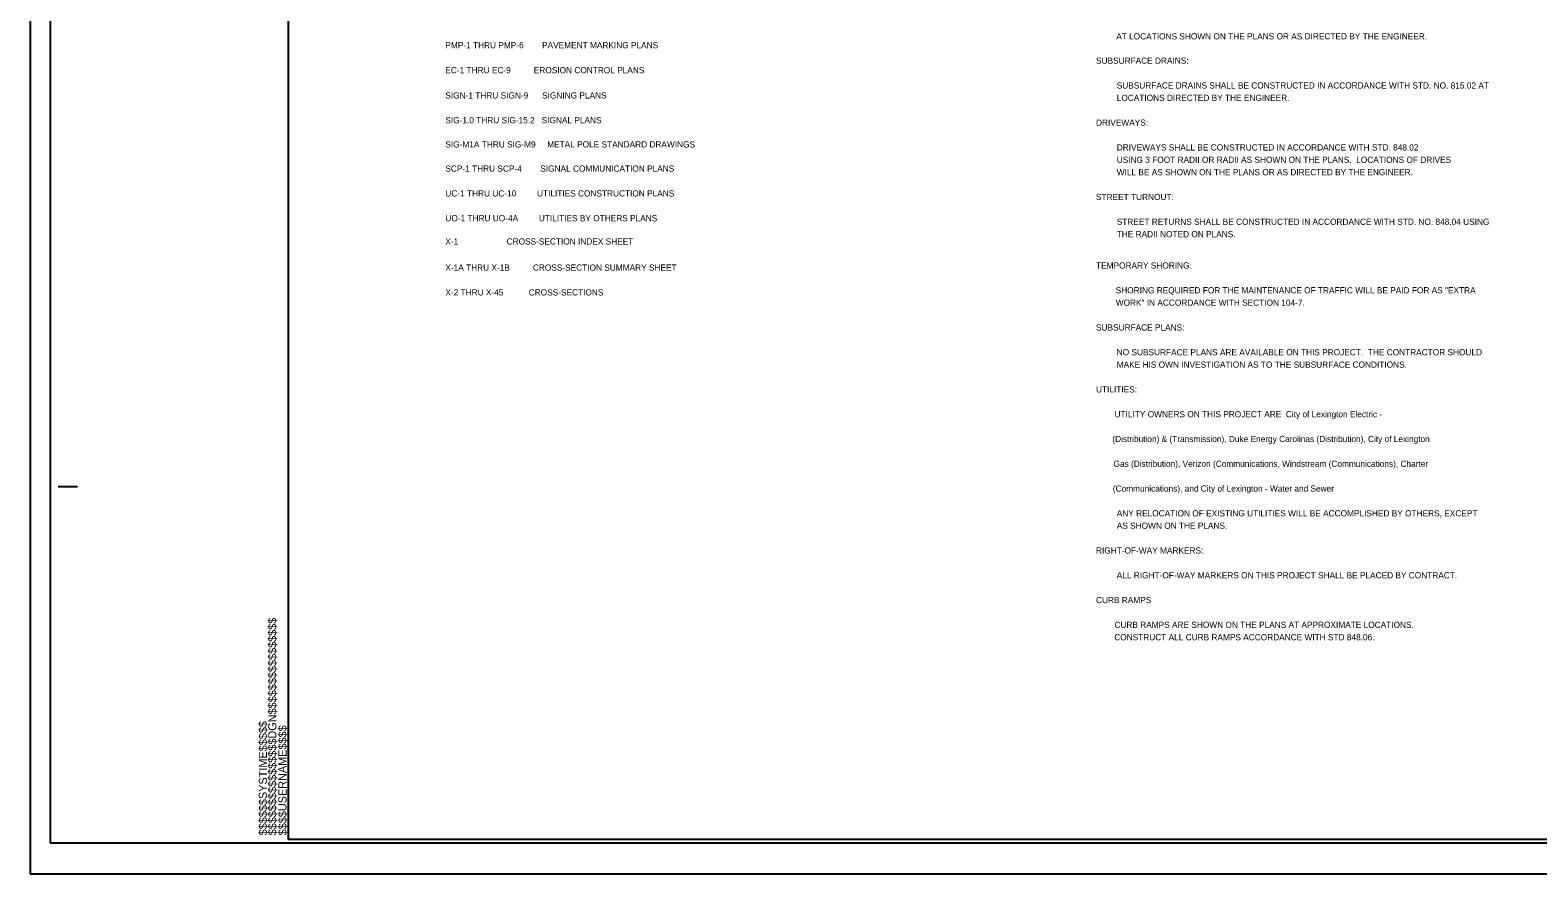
# Model space of a CAD drawing. Extents: x 1537922 to 1539606, y 409903 to 410998.
# Drawn here: x 1537922 to 1538895, y 409903 to 410448 of the extents above; entities that cross this region are included whole.
import ezdxf

# ---------------------------------------------------------------- set-up
doc = ezdxf.new("R2010")
doc.units = 0
for name, color, linetype in [('Default', 7, 'Continuous'), ('Sheet Cutting Line CELL', 7, 'Continuous'), ('Sheet Plan CELL', 7, 'Continuous'), ('Sheet Plot Border Inside CELL', 7, 'Continuous'), ('Sheet Plot Border Outside CELL', 7, 'Continuous')]:
    doc.layers.add(name, color=color, linetype=linetype)

msp = doc.modelspace()

# ---------------------------------------------------------------- linework, layer by layer
at = {"layer": 'Sheet Cutting Line CELL'}
for p, q in [((1537922.37, 410998.35), (1537922.37, 409903.35)), ((1537922.37, 409903.35), (1539605.87, 409903.35))]:
    msp.add_line(p, q, dxfattribs=at)
at = {"layer": 'Sheet Plan CELL'}
for p, q in [((1537940.37, 410153.35), (1537952.87, 410153.35)), ((1538088.87, 409925.85), (1538088.87, 409925.85))]:
    msp.add_line(p, q, dxfattribs=at)
msp.add_lwpolyline([(1539588.87, 410975.85), (1538088.87, 410975.85), (1538088.87, 409925.85), (1539588.87, 409925.85)], close=True, dxfattribs=at)
at = {"layer": 'Sheet Plot Border Inside CELL'}
msp.add_lwpolyline([(1537935.37, 409923.35), (1539601.37, 409923.35), (1539601.37, 410978.35), (1537935.37, 410978.35)], close=True, dxfattribs=at)
at = {"layer": 'Sheet Plot Border Outside CELL'}
msp.add_lwpolyline([(1537922.37, 409903.35), (1539605.87, 409903.35), (1539605.87, 410998.35), (1537922.37, 410998.35)], close=True, dxfattribs=at)

# ---------------------------------------------------------------- texts
at = {"layer": 'Default'}
for s, p in [('         AT LOCATIONS SHOWN ON THE PLANS OR AS DIRECTED BY THE ENGINEER.', (1538609.77, 410442.07)), ('PMP-1 THRU PMP-6        PAVEMENT MARKING PLANS', (1538190.28, 410436.34)), ('EC-1 THRU EC-9          EROSION CONTROL PLANS', (1538190.28, 410420.24)), ('SUBSURFACE DRAINS:', (1538610.1, 410426.36)), ('         SUBSURFACE DRAINS SHALL BE CONSTRUCTED IN ACCORDANCE WITH STD. NO. 815.02 AT ', (1538610.1, 410410.36)), ('SIGN-1 THRU SIGN-9      SIGNING PLANS', (1538190.28, 410403.93)), ('         LOCATIONS DIRECTED BY THE ENGINEER.  ', (1538610.1, 410402.36)), ('SIG-1.0 THRU SIG-15.2   SIGNAL PLANS', (1538190.28, 410387.93)), ('DRIVEWAYS:  ', (1538610.1, 410386.36)), ('SIG-M1A THRU SIG-M9     METAL POLE STANDARD DRAWINGS', (1538190.28, 410372.31)), ('         DRIVEWAYS SHALL BE CONSTRUCTED IN ACCORDANCE WITH STD. 848.02', (1538610.1, 410370.36)), ('         USING 3 FOOT RADII OR RADII AS SHOWN ON THE PLANS.  LOCATIONS OF DRIVES', (1538610.1, 410362.36)), ('SCP-1 THRU SCP-4        SIGNAL COMMUNICATION PLANS', (1538190.28, 410356.69)), ('         WILL BE AS SHOWN ON THE PLANS OR AS DIRECTED BY THE ENGINEER.  ', (1538610.1, 410354.36)), ('UC-1 THRU UC-10         UTILITIES CONSTRUCTION PLANS', (1538190.28, 410340.67)), ('STREET TURNOUT:  ', (1538610.1, 410338.36)), ('UO-1 THRU UO-4A         UTILITIES BY OTHERS PLANS', (1538190.28, 410324.67)), ('         STREET RETURNS SHALL BE CONSTRUCTED IN ACCORDANCE WITH STD. NO. 848.04 USING ', (1538610.1, 410322.36)), ('         THE RADII NOTED ON PLANS.  ', (1538610.1, 410314.36)), ('X-1                     CROSS-SECTION INDEX SHEET', (1538190.28, 410309.66)), ('X-1A THRU X-1B          CROSS-SECTION SUMMARY SHEET', (1538190.28, 410292.77)), ('TEMPORARY SHORING:  ', (1538610.1, 410294.13)), ('X-2 THRU X-45           CROSS-SECTIONS', (1538190.28, 410276.77)), ('         SHORING REQUIRED FOR THE MAINTENANCE OF TRAFFIC WILL BE PAID FOR AS "EXTRA', (1538609.44, 410278.13)), ('         WORK" IN ACCORDANCE WITH SECTION 104-7.', (1538609.46, 410270.13)), ('SUBSURFACE PLANS:  ', (1538610.1, 410254.13)), ('         NO SUBSURFACE PLANS ARE AVAILABLE ON THIS PROJECT.  THE CONTRACTOR SHOULD ', (1538610.1, 410238.13)), ('         MAKE HIS OWN INVESTIGATION AS TO THE SUBSURFACE CONDITIONS.  ', (1538610.1, 410230.13)), ('UTILITIES:  ', (1538610.1, 410214.13)), ('         UTILITY OWNERS ON THIS PROJECT ARE  City of Lexington Electric -', (1538608.68, 410198.13)), ('         (Distribution) & (Transmission), Duke Energy Carolinas (Distribution), City of Lexington', (1538607.25, 410182.13)), ('         Gas (Distribution), Verizon (Communications, Windstream (Communications), Charter', (1538607.99, 410166.13)), ('         (Communications), and City of Lexington - Water and Sewer', (1538607.58, 410150.13)), ('         ANY RELOCATION OF EXISTING UTILITIES WILL BE ACCOMPLISHED BY OTHERS, EXCEPT ', (1538610.1, 410134.13)), ('         AS SHOWN ON THE PLANS.  ', (1538610.1, 410126.13)), ('RIGHT-OF-WAY MARKERS:  ', (1538610.1, 410110.13)), ('         ALL RIGHT-OF-WAY MARKERS ON THIS PROJECT SHALL BE PLACED BY CONTRACT.  ', (1538610.1, 410094.13)), ('CURB RAMPS', (1538610.1, 410078.13)), ('        CURB RAMPS ARE SHOWN ON THE PLANS AT APPROXIMATE LOCATIONS.', (1538610.1, 410062.13)), ('        CONSTRUCT ALL CURB RAMPS ACCORDANCE WITH STD 848.06.', (1538609.99, 410054.13))]:
    msp.add_text(s, height=4, dxfattribs=at).set_placement(p)
at = {"layer": 'Sheet Plan CELL'}
for s, p in [('$$$$$$$$$$$$$$$$DGN$$$$$$$$$$$$$$$$', (1538081.22, 409928.21)), ('$$$$$$SYSTIME$$$$$', (1538075.17, 409928.21)), ('$$$$USERNAME$$$$', (1538087.79, 409928.23))]:
    msp.add_text(s, height=5.25, rotation=90, dxfattribs=at).set_placement(p)

doc.saveas('drawing.dxf')
